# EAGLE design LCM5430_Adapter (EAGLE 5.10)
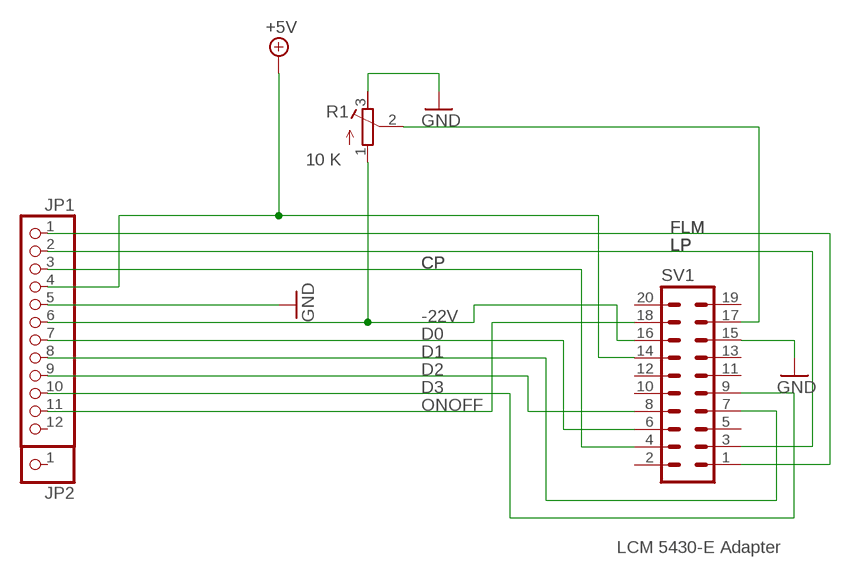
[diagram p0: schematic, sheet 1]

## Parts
JP1  PINHD-1X12  [1X12]
JP2  PINHD-1X1  [1X01]
R1  10 K  R-TRIMM64W  [RTRIM64W]
SV1  ML20  [ML20]

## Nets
+5V: JP1.4 SV1.14
-22V: JP1.6 R1.1(E) SV1.16
CP: JP1.3 SV1.4
D0: JP1.7 SV1.6
D1: JP1.8 SV1.7
D2: JP1.9 SV1.8
D3: JP1.10 SV1.9
FLM: JP1.1 SV1.1
GND: JP1.5 R1.3(A) SV1.15
LP: JP1.2 SV1.3
N$3: R1.2(S) SV1.17
ONOFF: JP1.11 SV1.18
Unconnected: JP1.12 JP2.1 SV1.2 SV1.5 SV1.10 SV1.11 SV1.12 SV1.13 SV1.19 SV1.20

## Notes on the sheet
- LCM 5430-E Adapter

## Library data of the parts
JP1 = pinhead:PINHD-1X12: PIN HEADER
JP2 = pinhead:PINHD-1X1: PIN HEADER
R1 = rcl:R-TRIMM: Trimm resistor
SV1 = con-harting-ml:ML20: HARTING

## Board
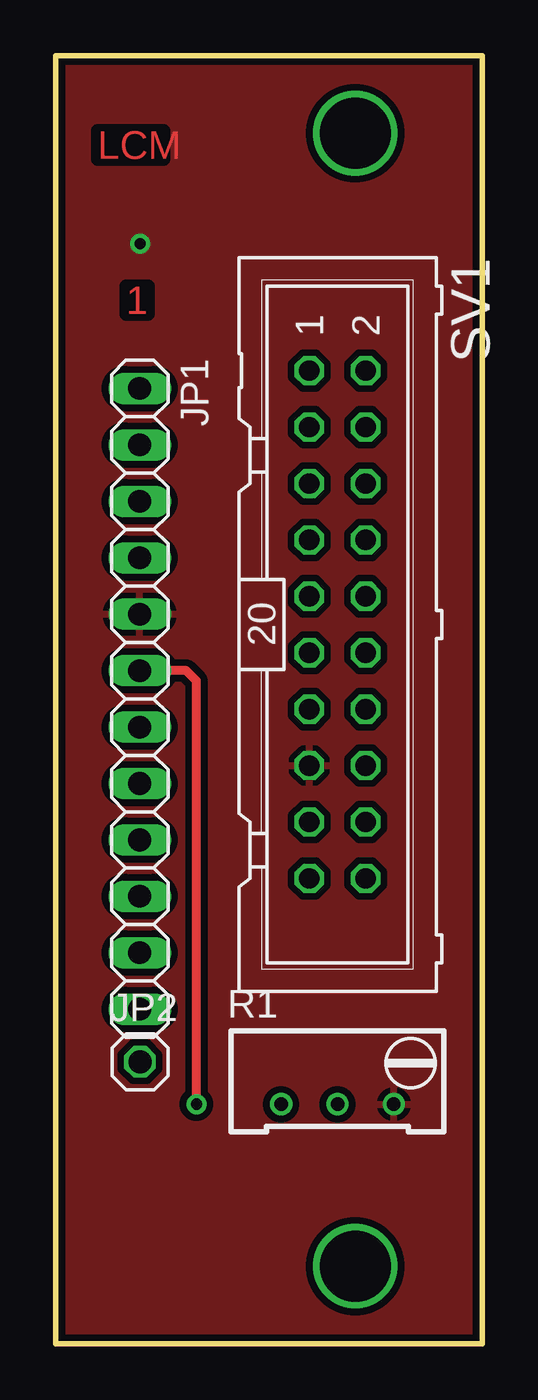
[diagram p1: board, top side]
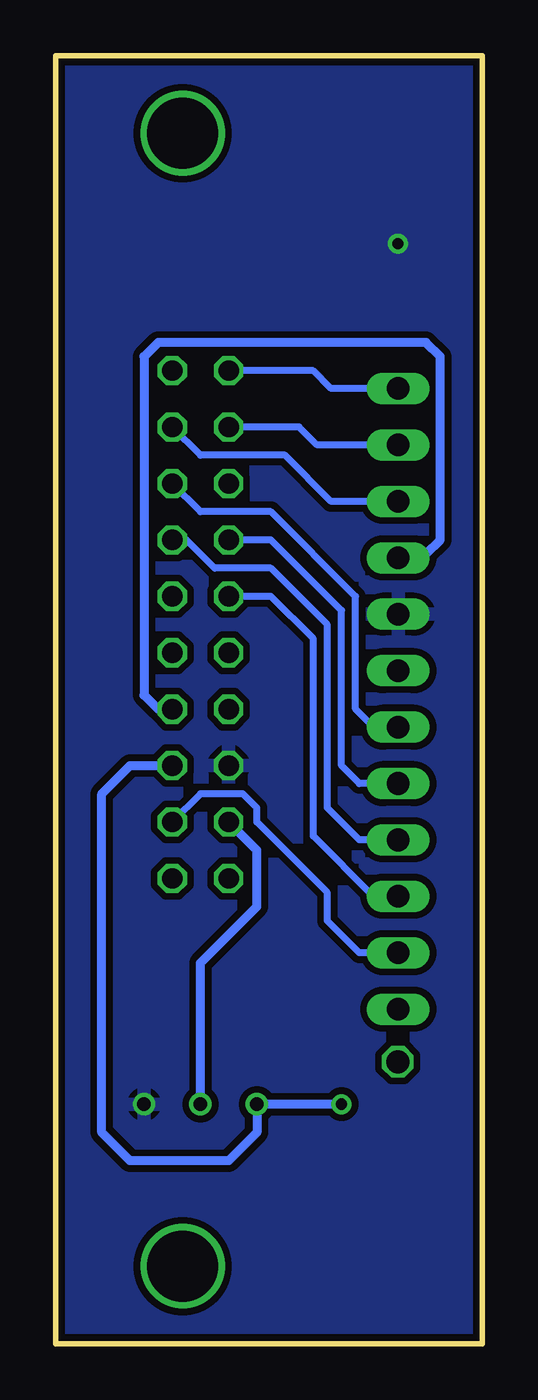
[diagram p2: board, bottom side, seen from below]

Size 19.23 x 58 mm. Coordinates in mm from the lower left corner, seen from the top.
Outline: 0,0 19.23,0 19.23,58 0,58 0,0
Copper layers (1*16): Top 0.035mm / dielectric 1.5mm / Bottom 0.035mm
Design rules "ZWILLING": minimum track width 0.2mm, minimum drill 0.5mm, track to track 0.2mm, track to pad 0.2mm, pad to pad 0.15mm, via to via 0.2mm, smd to smd 0mil, copper to edge 0.2mm, drill to drill 0.2mm, minimum pad ring 0.2mm, minimum via ring 0.2mm, stop-mask expansion 0.1mm, vias tented up to drill 0mil, thermal gap 10mil
bRestrict: 1 lines

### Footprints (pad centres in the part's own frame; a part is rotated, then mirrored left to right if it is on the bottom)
1X12 = drill 1.016 long: 1 -13.97,0; 2 -11.43,0; 3 -8.89,0; 4 -6.35,0; 5 -3.81,0; 6 -1.27,0; 7 1.27,0; 8 3.81,0; 9 6.35,0; 10 8.89,0; 11 11.43,0; 12 13.97,0
1X01 = drill 1.016 octagon: 1 0,0
RTRIM64W = drill 0.61 round: 1 1.27,-2.54; 2 1.27,0; 3 1.27,2.54
ML20 = drill 0.914 octagon: 1 -11.43,-1.27; 2 -11.43,1.27; 3 -8.89,-1.27; 4 -8.89,1.27; 5 -6.35,-1.27; 6 -6.35,1.27; 7 -3.81,-1.27; 8 -3.81,1.27; 9 -1.27,-1.27; 10 -1.27,1.27; 11 1.27,-1.27; 12 1.27,1.27; 13 3.81,-1.27; 14 3.81,1.27; 15 6.35,-1.27; 16 6.35,1.27; 17 8.89,-1.27; 18 8.89,1.27; 19 11.43,-1.27; 20 11.43,1.27

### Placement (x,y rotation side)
JP1  3.79,29.04 270 top
JP2  3.81,12.7 0 top
R1  12.7,12.06 270 top
SV1  12.7,32.38 270 top

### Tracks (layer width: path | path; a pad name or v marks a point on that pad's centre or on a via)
+5V
  Top 0.254: 3.81,35.56 3.79,35.56 JP1.4
  Bottom 0.305: 2.54,35.56 3.62,35.56 JP1.4
  Bottom 0.406: 2.54,35.56 1.9,36.2 1.9,44.45 2.54,45.09 14.61,45.09 15.24,44.45 15.24,29.21 14.61,28.57 SV1.14
-22V  (via drill 0.5)
  Top 0.254: 3.81,30.48 3.79,30.48 JP1.6
  Top 0.406: JP1.6 5.88,30.31 6.35,29.84 v6.35,10.79
  Bottom 0.406: SV1.16 15.88,26.04 17.14,24.77 17.14,9.53 15.88,8.26 11.43,8.26 10.16,9.53 R1.1 v6.35,10.79
CP
  Bottom 0.305: SV1.4 12.7,40.01 8.89,40.01 6.82,37.93 JP1.3
D0
  Bottom 0.305: JP1.7 4.91,27.77 5.71,28.57 5.71,33.66 9.53,37.47 12.7,37.47 SV1.6
D1
  Bottom 0.305: JP1.8 5.54,25.23 6.35,26.04 6.35,33.02 9.53,36.2 SV1.7
D2
  Bottom 0.305: JP1.9 5.54,22.69 6.99,24.13 6.99,32.38 9.53,34.92 12.07,34.92 13.34,36.2 SV1.8
D3
  Bottom 0.305: JP1.10 4.91,20.15 7.62,22.86 7.62,31.75 9.53,33.66 SV1.9
FLM
  Bottom 0.305: JP1.1 6.82,43.01 7.62,43.81 SV1.1
GND  (via drill 0.5)
  other vias: 3.81,49.53
  pour Bottom (isolate 0.305): -2.27,61 20.23,61 20.23,-2.5 -2.77,-2.5 -2.77,60.5
  pour Top (isolate 0.305): -2.27,58.5 20.23,58.5 20.23,-0.5 -2.27,-0.5
LP
  Bottom 0.305: JP1.2 7.45,40.47 8.26,41.27 SV1.3
N$3
  Bottom 0.406: SV1.17 10.16,22.23 10.16,19.68 12.7,17.14 R1.2
N$17  (via drill 3.2 pad 3.81)
  other vias: 13.5,54.5
N$25  (via drill 3.2 pad 3.81)
  other vias: 13.5,3.5
ONOFF
  Bottom 0.305: JP1.11 5.54,17.61 6.99,19.05 6.99,20.32 10.16,23.5 10.16,24.13 10.79,24.77 12.7,24.77 SV1.18

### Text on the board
Top: LCM | 1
